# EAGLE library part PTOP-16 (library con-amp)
AMP connector
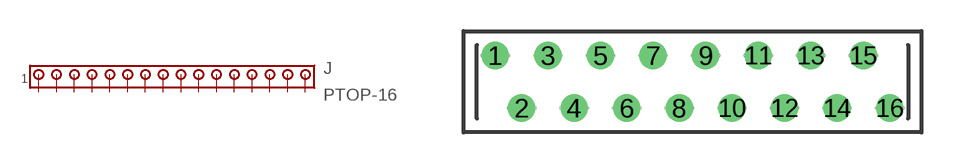
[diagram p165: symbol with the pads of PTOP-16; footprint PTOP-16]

Designator prefix J

## PTOP-16 (OC_FARNELL: unknown; OC_NEWARK: unknown)  [PTOP-16]
1  1  pas
2  2  pas
3  3  pas
4  4  pas
5  5  pas
6  6  pas
7  7  pas
8  8  pas
9  9  pas
10  10  pas
11  11  pas
12  12  pas
13  13  pas
14  14  pas
15  15  pas
16  16  pas

## Footprint PTOP-16 (pad centres in mm)
AMP connector
drill 0.813 round: 1 -9.525,1.27; 2 -8.255,-1.27; 3 -6.985,1.27; 4 -5.715,-1.27; 5 -4.445,1.27; 6 -3.175,-1.27; 7 -1.905,1.27; 8 -0.635,-1.27; 9 0.635,1.27; 10 1.905,-1.27; 11 3.175,1.27; 12 4.445,-1.27; 13 5.715,1.27; 14 6.985,-1.27; 15 8.255,1.27; 16 9.525,-1.27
